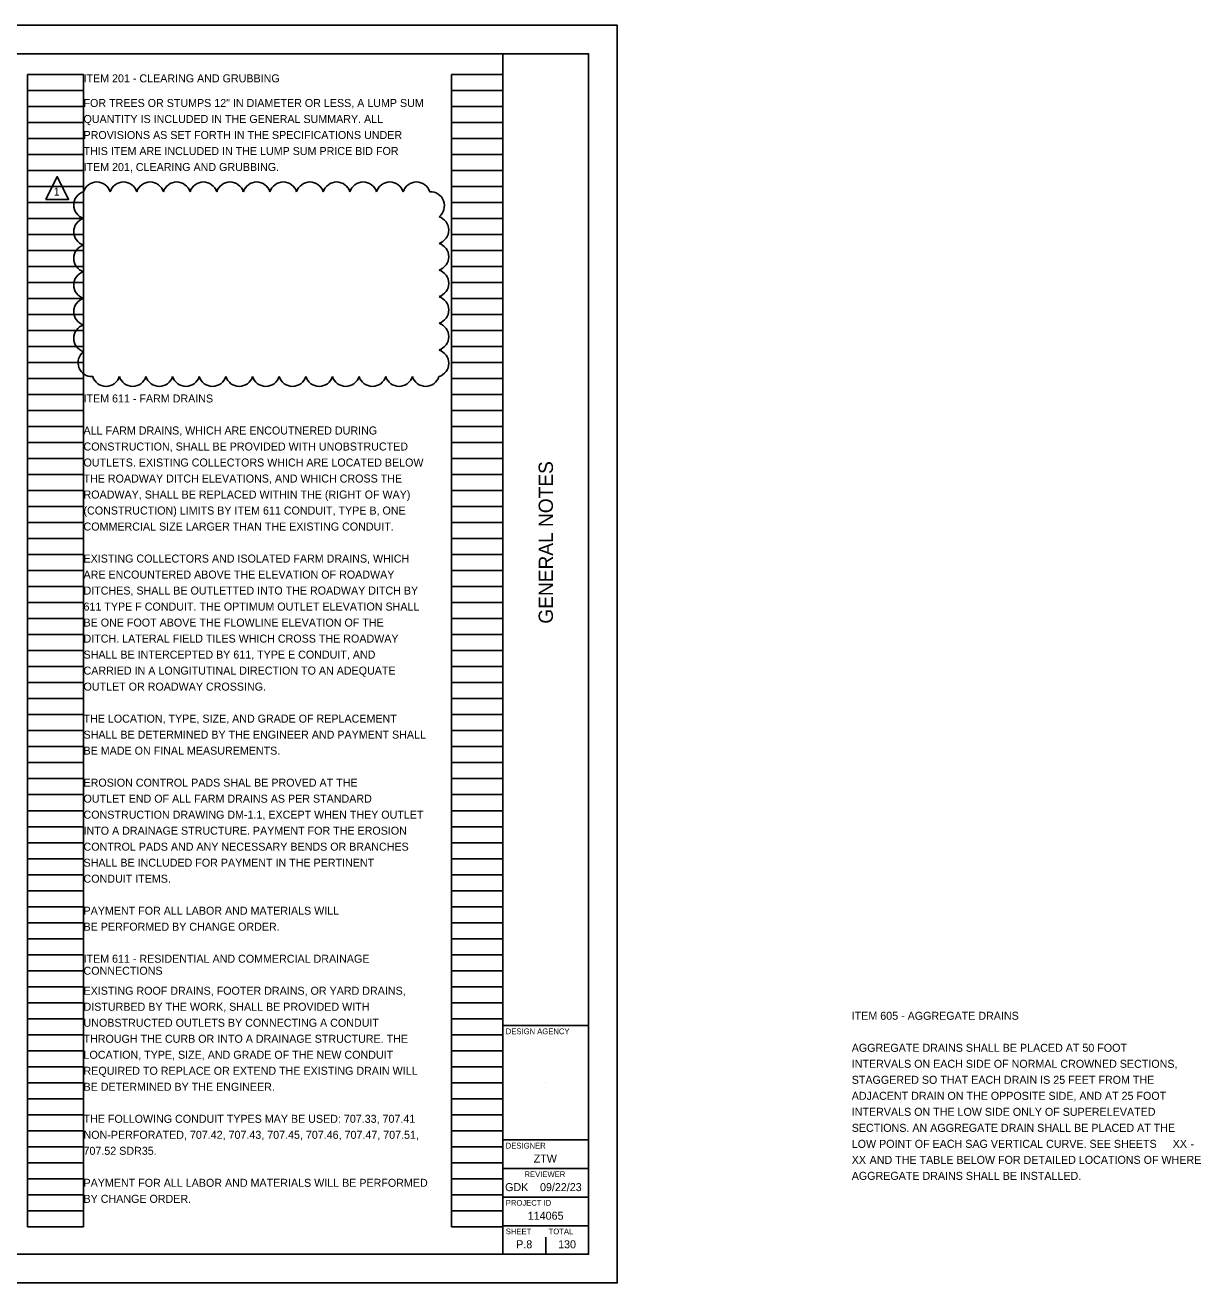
# Model space of a CAD drawing. Extents: x 0.1 to 44.3, y 0 to 22.
# Drawn here: x 23.75 to 44.33, y 0.05 to 22.05 of the extents above; entities that cross this region are included whole.
import ezdxf

# ---------------------------------------------------------------- set-up
doc = ezdxf.new("R2010")
doc.units = 0
for name, color, linetype in [('MU_Markup_Cloud', 7, 'Continuous'), ('SH_Border', 7, 'Continuous'), ('SH_Cut_Line', 7, 'Continuous'), ('SH_Data', 7, 'Continuous'), ('SH_Text', 7, 'Continuous')]:
    doc.layers.add(name, color=color, linetype=linetype)

msp = doc.modelspace()

# ---------------------------------------------------------------- linework, layer by layer
at = {"layer": 'MU_Markup_Cloud'}
msp.add_lwpolyline([(24.116, 18.997), (24.316, 19.397), (24.516, 18.997)], close=True, dxfattribs=at)
for centre, start, end in [((25.009, 19.058), 17.5, 162.5), ((25.475, 19.058), 17.5, 162.5), ((25.941, 19.058), 17.5, 162.5), ((26.407, 19.058), 17.5, 162.5), ((26.874, 19.058), 17.5, 162.5), ((27.34, 19.058), 17.5, 162.5), ((27.806, 19.058), 17.5, 162.5), ((28.272, 19.058), 17.5, 162.5), ((28.738, 19.058), 17.5, 162.5), ((29.205, 19.058), 17.5, 162.5), ((29.671, 19.058), 17.5, 162.5), ((30.137, 19.058), 17.5, 162.5), ((30.603, 19.058), 17.5, 162.5), ((24.849, 18.899), 107.5, 252.5), ((30.848, 18.888), 307.6996, 92.6996), ((24.849, 18.432), 107.5, 252.5), ((30.924, 18.461), 287.5, 72.5), ((24.849, 17.966), 107.5, 252.5), ((30.924, 17.995), 287.5, 72.5), ((24.849, 17.5), 107.5, 252.5), ((30.924, 17.529), 287.5, 72.5), ((24.849, 17.034), 107.5, 252.5), ((30.924, 17.063), 287.5, 72.5), ((24.849, 16.568), 107.5, 252.5), ((30.924, 16.597), 287.5, 72.5), ((24.925, 16.141), 127.6996, 272.6996), ((30.924, 16.13), 287.5, 72.5), ((25.17, 15.971), 197.5, 342.5), ((25.636, 15.971), 197.5, 342.5), ((26.102, 15.971), 197.5, 342.5), ((26.568, 15.971), 197.5, 342.5), ((27.034, 15.971), 197.5, 342.5), ((27.501, 15.971), 197.5, 342.5), ((27.967, 15.971), 197.5, 342.5), ((28.433, 15.971), 197.5, 342.5), ((28.899, 15.971), 197.5, 342.5), ((29.365, 15.971), 197.5, 342.5), ((29.832, 15.971), 197.5, 342.5), ((30.298, 15.971), 197.5, 342.5), ((30.764, 15.971), 197.5, 342.5)]:
    msp.add_arc(centre, 0.244, start, end, dxfattribs=at)
at = {"layer": 'SH_Border'}
for p, q in [((32.116, 0.545), (32.116, 21.545)), ((32.116, 4.545), (33.616, 4.545)), ((32.116, 2.545), (33.616, 2.545)), ((32.116, 2.045), (33.616, 2.045)), ((32.116, 1.545), (33.616, 1.545)), ((32.116, 1.045), (33.616, 1.045))]:
    msp.add_line(p, q, dxfattribs=at)
msp.add_lwpolyline([(1.616, 21.545), (33.616, 21.545), (33.616, 0.545), (1.616, 0.545)], close=True, dxfattribs=at)
at = {"layer": 'SH_Cut_Line'}
msp.add_lwpolyline([(0.116, 0.045), (34.116, 0.045), (34.116, 22.045), (0.116, 22.045)], close=True, dxfattribs=at)
at = {"layer": 'SH_Data'}
for p, q in [((23.796, 1.025), (23.796, 21.185)), ((23.796, 21.185), (24.776, 21.185)), ((24.776, 1.025), (24.776, 21.185)), ((31.216, 1.025), (31.216, 21.185)), ((31.216, 21.185), (32.116, 21.185)), ((32.116, 1.025), (32.116, 21.185)), ((23.796, 20.905), (24.776, 20.905)), ((31.216, 20.905), (32.116, 20.905)), ((23.796, 20.625), (24.776, 20.625)), ((31.216, 20.625), (32.116, 20.625)), ((23.796, 20.345), (24.776, 20.345)), ((31.216, 20.345), (32.116, 20.345)), ((23.796, 20.065), (24.776, 20.065)), ((31.216, 20.065), (32.116, 20.065)), ((23.796, 19.785), (24.776, 19.785)), ((31.216, 19.785), (32.116, 19.785)), ((23.796, 19.505), (24.776, 19.505)), ((31.216, 19.505), (32.116, 19.505)), ((23.796, 19.225), (24.776, 19.225)), ((31.216, 19.225), (32.116, 19.225)), ((23.796, 18.945), (24.776, 18.945)), ((31.216, 18.945), (32.116, 18.945)), ((23.796, 18.665), (24.776, 18.665)), ((31.216, 18.665), (32.116, 18.665)), ((23.796, 18.385), (24.776, 18.385)), ((31.216, 18.385), (32.116, 18.385)), ((23.796, 18.105), (24.776, 18.105)), ((31.216, 18.105), (32.116, 18.105)), ((23.796, 17.825), (24.776, 17.825)), ((31.216, 17.825), (32.116, 17.825)), ((23.796, 17.545), (24.776, 17.545)), ((31.216, 17.545), (32.116, 17.545)), ((23.796, 17.265), (24.776, 17.265)), ((31.216, 17.265), (32.116, 17.265)), ((23.796, 16.985), (24.776, 16.985)), ((31.216, 16.985), (32.116, 16.985)), ((23.796, 16.705), (24.776, 16.705)), ((31.216, 16.705), (32.116, 16.705)), ((23.796, 16.425), (24.776, 16.425)), ((31.216, 16.425), (32.116, 16.425)), ((23.796, 16.145), (24.776, 16.145)), ((31.216, 16.145), (32.116, 16.145)), ((23.796, 15.865), (24.776, 15.865)), ((31.216, 15.865), (32.116, 15.865)), ((23.796, 15.585), (24.776, 15.585)), ((31.216, 15.585), (32.116, 15.585)), ((23.796, 15.305), (24.776, 15.305)), ((31.216, 15.305), (32.116, 15.305)), ((23.796, 15.025), (24.776, 15.025)), ((31.216, 15.025), (32.116, 15.025)), ((23.796, 14.745), (24.776, 14.745)), ((31.216, 14.745), (32.116, 14.745)), ((23.796, 14.465), (24.776, 14.465)), ((31.216, 14.465), (32.116, 14.465)), ((23.796, 14.185), (24.776, 14.185)), ((31.216, 14.185), (32.116, 14.185)), ((23.796, 13.905), (24.776, 13.905)), ((31.216, 13.905), (32.116, 13.905)), ((23.796, 13.625), (24.776, 13.625)), ((31.216, 13.625), (32.116, 13.625)), ((23.796, 13.345), (24.776, 13.345)), ((31.216, 13.345), (32.116, 13.345)), ((23.796, 13.065), (24.776, 13.065)), ((31.216, 13.065), (32.116, 13.065)), ((23.796, 12.785), (24.776, 12.785)), ((31.216, 12.785), (32.116, 12.785)), ((23.796, 12.505), (24.776, 12.505)), ((31.216, 12.505), (32.116, 12.505)), ((23.796, 12.225), (24.776, 12.225)), ((31.216, 12.225), (32.116, 12.225)), ((23.796, 11.945), (24.776, 11.945)), ((31.216, 11.945), (32.116, 11.945)), ((23.796, 11.665), (24.776, 11.665)), ((31.216, 11.665), (32.116, 11.665)), ((23.796, 11.385), (24.776, 11.385)), ((31.216, 11.385), (32.116, 11.385)), ((23.796, 11.105), (24.776, 11.105)), ((31.216, 11.105), (32.116, 11.105)), ((23.796, 10.825), (24.776, 10.825)), ((31.216, 10.825), (32.116, 10.825)), ((23.796, 10.545), (24.776, 10.545)), ((31.216, 10.545), (32.116, 10.545)), ((23.796, 10.265), (24.776, 10.265)), ((31.216, 10.265), (32.116, 10.265)), ((23.796, 9.985), (24.776, 9.985)), ((31.216, 9.985), (32.116, 9.985)), ((23.796, 9.705), (24.776, 9.705)), ((31.216, 9.705), (32.116, 9.705)), ((23.796, 9.425), (24.776, 9.425)), ((31.216, 9.425), (32.116, 9.425)), ((23.796, 9.145), (24.776, 9.145)), ((31.216, 9.145), (32.116, 9.145)), ((23.796, 8.865), (24.776, 8.865)), ((31.216, 8.865), (32.116, 8.865)), ((23.796, 8.585), (24.776, 8.585)), ((31.216, 8.585), (32.116, 8.585)), ((23.796, 8.305), (24.776, 8.305)), ((31.216, 8.305), (32.116, 8.305)), ((23.796, 8.025), (24.776, 8.025)), ((31.216, 8.025), (32.116, 8.025)), ((23.796, 7.745), (24.776, 7.745)), ((31.216, 7.745), (32.116, 7.745)), ((23.796, 7.465), (24.776, 7.465)), ((31.216, 7.465), (32.116, 7.465)), ((23.796, 7.185), (24.776, 7.185)), ((31.216, 7.185), (32.116, 7.185)), ((23.796, 6.905), (24.776, 6.905)), ((31.216, 6.905), (32.116, 6.905)), ((23.796, 6.625), (24.776, 6.625)), ((31.216, 6.625), (32.116, 6.625)), ((23.796, 6.345), (24.776, 6.345)), ((31.216, 6.345), (32.116, 6.345)), ((23.796, 6.065), (24.776, 6.065)), ((31.216, 6.065), (32.116, 6.065)), ((23.796, 5.785), (24.776, 5.785)), ((31.216, 5.785), (32.116, 5.785)), ((23.796, 5.505), (24.776, 5.505)), ((31.216, 5.505), (32.116, 5.505)), ((23.796, 5.225), (24.776, 5.225)), ((31.216, 5.225), (32.116, 5.225)), ((23.796, 4.945), (24.776, 4.945)), ((31.216, 4.945), (32.116, 4.945)), ((23.796, 4.665), (24.776, 4.665)), ((31.216, 4.665), (32.116, 4.665)), ((23.796, 4.385), (24.776, 4.385)), ((31.216, 4.385), (32.116, 4.385)), ((23.796, 4.105), (24.776, 4.105)), ((31.216, 4.105), (32.116, 4.105)), ((23.796, 3.825), (24.776, 3.825)), ((31.216, 3.825), (32.116, 3.825)), ((23.796, 3.545), (24.776, 3.545)), ((31.216, 3.545), (32.116, 3.545)), ((32.866, 3.545), (32.866, 3.545)), ((23.796, 3.265), (24.776, 3.265)), ((31.216, 3.265), (32.116, 3.265)), ((23.796, 2.985), (24.776, 2.985)), ((31.216, 2.985), (32.116, 2.985)), ((23.796, 2.705), (24.776, 2.705)), ((31.216, 2.705), (32.116, 2.705)), ((23.796, 2.425), (24.776, 2.425)), ((31.216, 2.425), (32.116, 2.425)), ((23.796, 2.145), (24.776, 2.145)), ((31.216, 2.145), (32.116, 2.145)), ((23.796, 1.865), (24.776, 1.865)), ((31.216, 1.865), (32.116, 1.865)), ((23.796, 1.585), (24.776, 1.585)), ((31.216, 1.585), (32.116, 1.585)), ((23.796, 1.305), (24.776, 1.305)), ((31.216, 1.305), (32.116, 1.305)), ((23.796, 1.025), (24.776, 1.025)), ((31.216, 1.025), (32.116, 1.025)), ((32.491, 0.72), (32.491, 0.72)), ((32.866, 0.545), (32.866, 0.845))]:
    msp.add_line(p, q, dxfattribs=at)

# ---------------------------------------------------------------- texts
at = {"layer": 'MU_Markup_Cloud'}
msp.add_text('1', height=0.14, dxfattribs=at).set_placement((24.254, 19.063))
at = {"layer": 'SH_Data'}
msp.add_text('GENERAL NOTES', height=0.25, rotation=90, dxfattribs=at).set_placement((32.991, 11.576))
for s, height, p in [('DESIGN AGENCY', 0.1, (32.166, 4.395)), ('DESIGNER', 0.1, (32.166, 2.395)), ('ZTW', 0.14, (32.655, 2.15)), ('REVIEWER', 0.1, (32.494, 1.895)), ('GDK', 0.14, (32.154, 1.65)), ('09/22/23', 0.14, (32.765, 1.65)), ('PROJECT ID', 0.1, (32.166, 1.395)), ('114065', 0.14, (32.551, 1.15)), ('SHEET', 0.1, (32.166, 0.895)), ('TOTAL', 0.1, (32.916, 0.895)), ('P.8', 0.14, (32.348, 0.65)), ('130', 0.14, (33.082, 0.65))]:
    msp.add_text(s, height=height, dxfattribs=at).set_placement(p)
at = {"layer": 'SH_Text'}
for s, p in [('ITEM 201 - CLEARING AND GRUBBING', (24.776, 21.045)), ('FOR TREES OR STUMPS 12" IN DIAMETER OR LESS, A LUMP SUM ', (24.776, 20.614)), ('QUANTITY IS INCLUDED IN THE GENERAL SUMMARY. ALL ', (24.776, 20.334)), ('PROVISIONS AS SET FORTH IN THE SPECIFICATIONS UNDER ', (24.776, 20.054)), ('THIS ITEM ARE INCLUDED IN THE LUMP SUM PRICE BID FOR ', (24.776, 19.774)), ('ITEM 201, CLEARING AND GRUBBING.', (24.776, 19.494)), ('ITEM 611 - FARM DRAINS', (24.776, 15.445)), ('ALL FARM DRAINS, WHICH ARE ENCOUTNERED DURING', (24.776, 14.885)), ('CONSTRUCTION, SHALL BE PROVIDED WITH UNOBSTRUCTED', (24.776, 14.605)), ('OUTLETS. EXISTING COLLECTORS WHICH ARE LOCATED BELOW ', (24.776, 14.325)), ('THE ROADWAY DITCH ELEVATIONS, AND WHICH CROSS THE', (24.776, 14.045)), ('ROADWAY, SHALL BE REPLACED WITHIN THE (RIGHT OF WAY)', (24.776, 13.765)), ('(CONSTRUCTION) LIMITS BY ITEM 611 CONDUIT, TYPE B, ONE', (24.776, 13.485)), ('COMMERCIAL SIZE LARGER THAN THE EXISTING CONDUIT.', (24.776, 13.205)), ('EXISTING COLLECTORS AND ISOLATED FARM DRAINS, WHICH ', (24.776, 12.645)), ('ARE ENCOUNTERED ABOVE THE ELEVATION OF ROADWAY', (24.776, 12.365)), ('DITCHES, SHALL BE OUTLETTED INTO THE ROADWAY DITCH BY ', (24.776, 12.085)), ('611 TYPE F CONDUIT. THE OPTIMUM OUTLET ELEVATION SHALL', (24.776, 11.805)), ('BE ONE FOOT ABOVE THE FLOWLINE ELEVATION OF THE', (24.776, 11.525)), ('DITCH. LATERAL FIELD TILES WHICH CROSS THE ROADWAY', (24.776, 11.245)), ('SHALL BE INTERCEPTED BY 611, TYPE E CONDUIT, AND', (24.776, 10.965)), ('CARRIED IN A LONGITUTINAL DIRECTION TO AN ADEQUATE', (24.776, 10.685)), ('OUTLET OR ROADWAY CROSSING.', (24.776, 10.405)), ('THE LOCATION, TYPE, SIZE, AND GRADE OF REPLACEMENT', (24.776, 9.845)), ('SHALL BE DETERMINED BY THE ENGINEER AND PAYMENT SHALL', (24.776, 9.565)), ('BE MADE ON FINAL MEASUREMENTS.', (24.776, 9.285)), ('EROSION CONTROL PADS SHAL BE PROVED AT THE ', (24.776, 8.725)), ('OUTLET END OF ALL FARM DRAINS AS PER STANDARD', (24.776, 8.445)), ('CONSTRUCTION DRAWING DM-1.1, EXCEPT WHEN THEY OUTLET', (24.776, 8.165)), ('INTO A DRAINAGE STRUCTURE. PAYMENT FOR THE EROSION', (24.776, 7.885)), ('CONTROL PADS AND ANY NECESSARY BENDS OR BRANCHES', (24.776, 7.605)), ('SHALL BE INCLUDED FOR PAYMENT IN THE PERTINENT', (24.776, 7.325)), ('CONDUIT ITEMS.', (24.776, 7.045)), ('PAYMENT FOR ALL LABOR AND MATERIALS WILL', (24.776, 6.485)), ('BE PERFORMED BY CHANGE ORDER.', (24.776, 6.205)), ('ITEM 611 - RESIDENTIAL AND COMMERCIAL DRAINAGE ', (24.776, 5.645)), ('CONNECTIONS', (24.776, 5.435)), ('EXISTING ROOF DRAINS, FOOTER DRAINS, OR YARD DRAINS, ', (24.776, 5.085)), ('DISTURBED BY THE WORK, SHALL BE PROVIDED WITH ', (24.776, 4.805)), ('UNOBSTRUCTED OUTLETS BY CONNECTING A CONDUIT ', (24.776, 4.525)), ('ITEM 605 - AGGREGATE DRAINS', (38.22, 4.647)), ('THROUGH THE CURB OR INTO A DRAINAGE STRUCTURE. THE ', (24.776, 4.245)), ('AGGREGATE DRAINS SHALL BE PLACED AT 50 FOOT', (38.22, 4.087)), ('LOCATION, TYPE, SIZE, AND GRADE OF THE NEW CONDUIT ', (24.776, 3.965)), ('REQUIRED TO REPLACE OR EXTEND THE EXISTING DRAIN WILL ', (24.776, 3.685)), ('INTERVALS ON EACH SIDE OF NORMAL CROWNED SECTIONS,', (38.22, 3.807)), ('BE DETERMINED BY THE ENGINEER.', (24.776, 3.405)), ('STAGGERED SO THAT EACH DRAIN IS 25 FEET FROM THE', (38.22, 3.527)), ('ADJACENT DRAIN ON THE OPPOSITE SIDE, AND AT 25 FOOT', (38.22, 3.247)), ('INTERVALS ON THE LOW SIDE ONLY OF SUPERELEVATED ', (38.22, 2.967)), ('THE FOLLOWING CONDUIT TYPES MAY BE USED: 707.33, 707.41 ', (24.776, 2.845)), ('NON-PERFORATED, 707.42, 707.43, 707.45, 707.46, 707.47, 707.51, ', (24.776, 2.565)), ('SECTIONS. AN AGGREGATE DRAIN SHALL BE PLACED AT THE', (38.22, 2.687)), ('707.52 SDR35.', (24.776, 2.285)), ('LOW POINT OF EACH SAG VERTICAL CURVE. SEE SHEETS ', (38.22, 2.407)), ('XX', (43.837, 2.407)), (' -', (44.098, 2.407)), ('XX', (38.22, 2.127)), (' AND THE TABLE BELOW FOR DETAILED LOCATIONS OF WHERE', (38.481, 2.127)), ('AGGREGATE DRAINS SHALL BE INSTALLED.', (38.22, 1.847)), ('PAYMENT FOR ALL LABOR AND MATERIALS WILL BE PERFORMED ', (24.776, 1.725)), ('BY CHANGE ORDER.', (24.776, 1.445))]:
    msp.add_text(s, height=0.14, dxfattribs=at).set_placement(p)

doc.saveas('drawing.dxf')
